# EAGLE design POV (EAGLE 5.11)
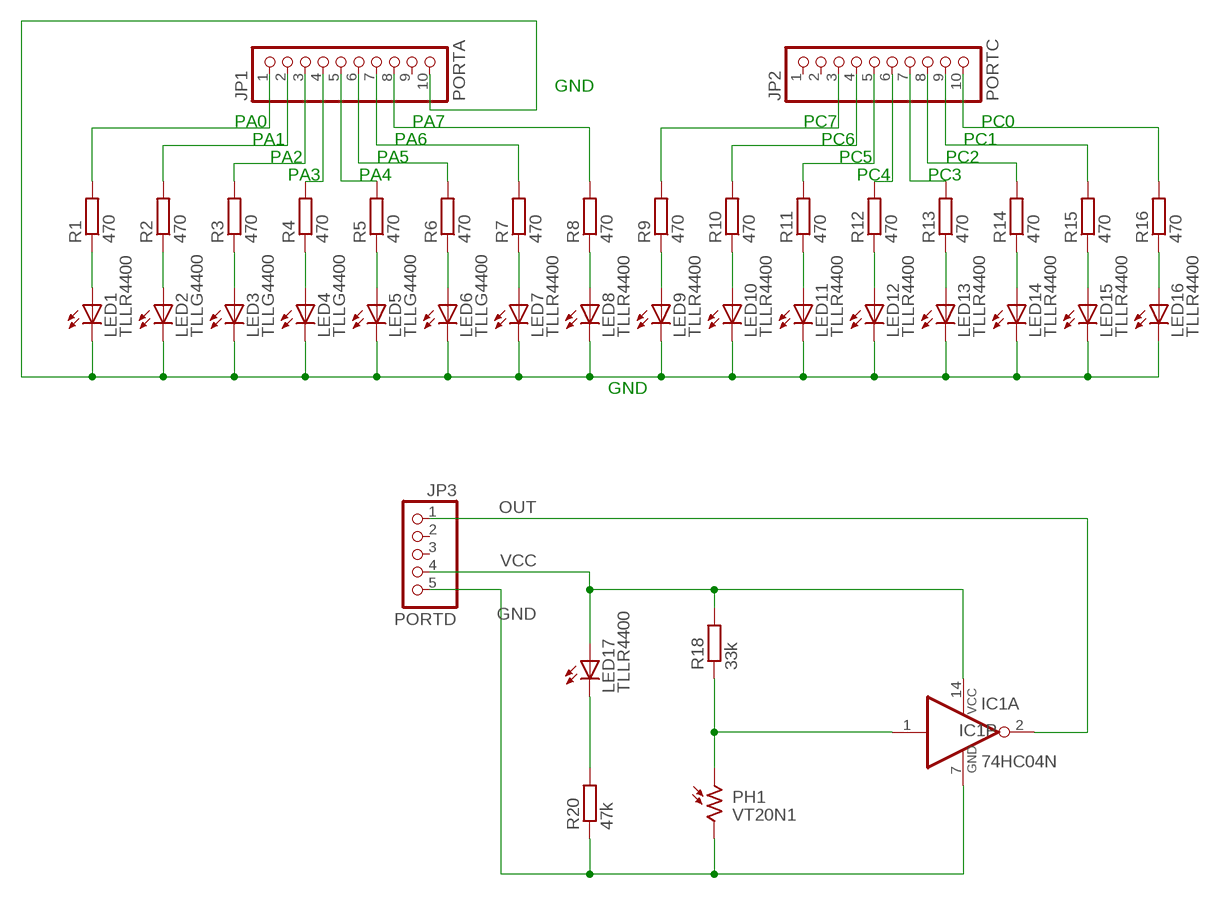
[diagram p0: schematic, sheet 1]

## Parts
IC1  74HC04N  [DIL14]
JP1  PORTA  PINHD-1X10  [1X10]
JP2  PORTC  PINHD-1X10  [1X10]
JP3  PORTD  PINHD-1X5  [1X05]
LED1  TLLR4400  LED5MM  [LED5MM]
LED2  TLLG4400  LED5MM  [LED5MM]
LED3  TLLG4400  LED5MM  [LED5MM]
LED4  TLLG4400  LED5MM  [LED5MM]
LED5  TLLG4400  LED5MM  [LED5MM]
LED6  TLLG4400  LED5MM  [LED5MM]
LED7  TLLR4400  LED5MM  [LED5MM]
LED8  TLLR4400  LED5MM  [LED5MM]
LED9  TLLR4400  LED5MM  [LED5MM]
LED10  TLLR4400  LED5MM  [LED5MM]
LED11  TLLR4400  LED5MM  [LED5MM]
LED12  TLLR4400  LED5MM  [LED5MM]
LED13  TLLR4400  LED5MM  [LED5MM]
LED14  TLLR4400  LED5MM  [LED5MM]
LED15  TLLR4400  LED5MM  [LED5MM]
LED16  TLLR4400  LED5MM  [LED5MM]
LED17  TLLR4400  LED5MM  [LED5MM]
PH1  VT20N1  [TO46-VT200]
R1  470  R-EU_0207/10  [0207/10]
R2  470  R-EU_0207/10  [0207/10]
R3  470  R-EU_0207/10  [0207/10]
R4  470  R-EU_0207/10  [0207/10]
R5  470  R-EU_0207/10  [0207/10]
R6  470  R-EU_0207/10  [0207/10]
R7  470  R-EU_0207/10  [0207/10]
R8  470  R-EU_0207/10  [0207/10]
R9  470  R-EU_0207/10  [0207/10]
R10  470  R-EU_0207/10  [0207/10]
R11  470  R-EU_0207/10  [0207/10]
R12  470  R-EU_0207/10  [0207/10]
R13  470  R-EU_0207/10  [0207/10]
R14  470  R-EU_0207/10  [0207/10]
R15  470  R-EU_0207/10  [0207/10]
R16  470  R-EU_0207/10  [0207/10]
R18  33k  R-EU_0207/10  [0207/10]
R20  47k  R-EU_0207/10  [0207/10]

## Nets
GND: IC1.7(P:GND) JP3.5 PH1.2 R20.1
N$1: LED1.A R1.1
N$2: LED2.A R2.1
N$3: LED3.A R3.1
N$4: LED4.A R4.1
N$5: LED5.A R5.1
N$6: LED6.A R6.1
N$7: LED7.A R7.1
N$8: LED8.A R8.1
N$9: LED9.A R9.1
N$10: LED10.A R10.1
N$11: LED11.A R11.1
N$12: LED12.A R12.1
N$13: JP1.7 R7.2
N$14: JP1.8 R8.2
N$15: JP1.3 R3.2
N$16: JP1.4 R4.2
N$17: JP1.5 R5.2
N$18: JP1.6 R6.2
N$19: JP1.2 R2.2
N$20: JP1.1 R1.2
N$21: LED17.K(C) R20.2
N$22: JP2.5 R11.2
N$23: JP2.4 R10.2
N$24: JP2.3 R9.2
N$25: LED13.A R13.1
N$26: LED14.A R14.1
N$27: LED15.A R15.1
N$28: LED16.A R16.1
N$29: JP2.7 R13.2
N$30: JP2.8 R14.2
N$31: JP2.9 R15.2
N$32: JP2.10 R16.2
N$33: JP1.10 LED1.K(C) LED2.K(C) LED3.K(C) LED4.K(C) LED5.K(C) LED6.K(C) LED7.K(C) LED8.K(C) LED9.K(C) LED10.K(C) LED11.K(C) LED12.K(C) LED13.K(C) LED14.K(C) LED15.K(C) LED16.K(C)
N$34: JP2.6 R12.2
N$37: IC1.1(A:I) PH1.1 R18.1
OUT: IC1.2(A:O) JP3.1
VCC: IC1.14(P:VCC) JP3.4 LED17.A R18.2
Unconnected: IC1.3(B:I) IC1.4(B:O) IC1.5(C:I) IC1.6(C:O) IC1.8(D:O) IC1.9(D:I) IC1.10(E:O) IC1.11(E:I) IC1.12(F:O) IC1.13(F:I) JP1.9 JP2.1 JP2.2 JP3.2 JP3.3

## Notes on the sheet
- GND
- PA0 | PA7 | PC7 | PC0
- PA1 | PA6 | PC6 | PC1
- PA2 | PA5 | PC5 | PC2
- PA3 | PA4 | PC4 | PC3
- GND

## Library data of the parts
IC1 = 74xx-eu:74*04: Hex INVERTER
JP1 JP2 = pinhead:PINHD-1X10: PIN HEADER
JP3 = pinhead:PINHD-1X5: PIN HEADER
LED1-LED17 = led:LED: LED
PH1 = photo-elements:VT2*: Photoconductive Cell VT200 Series
R1-R16 R18 R20 = resistor:R-EU_: RESISTOR, European symbol

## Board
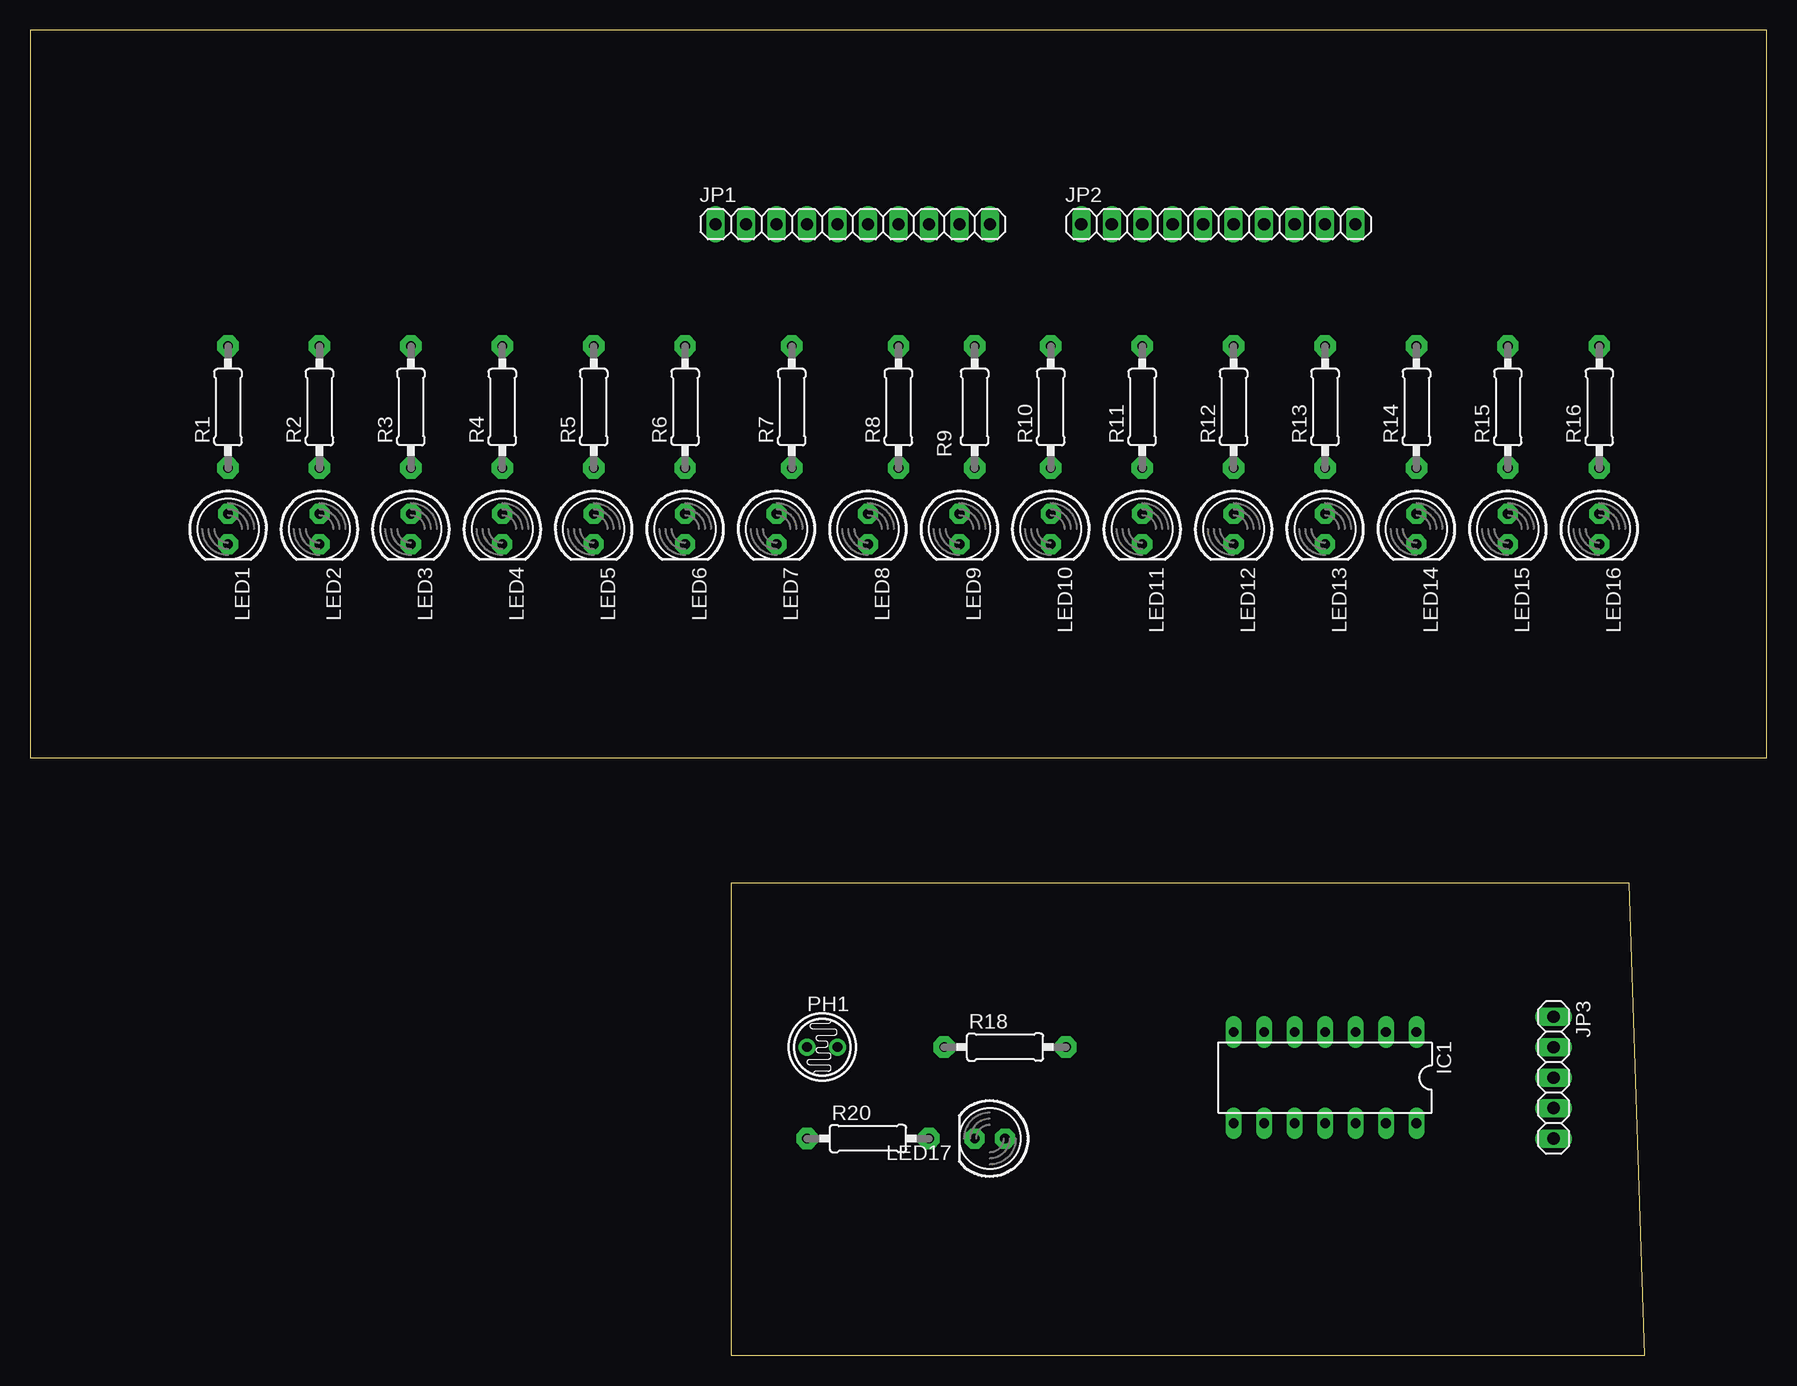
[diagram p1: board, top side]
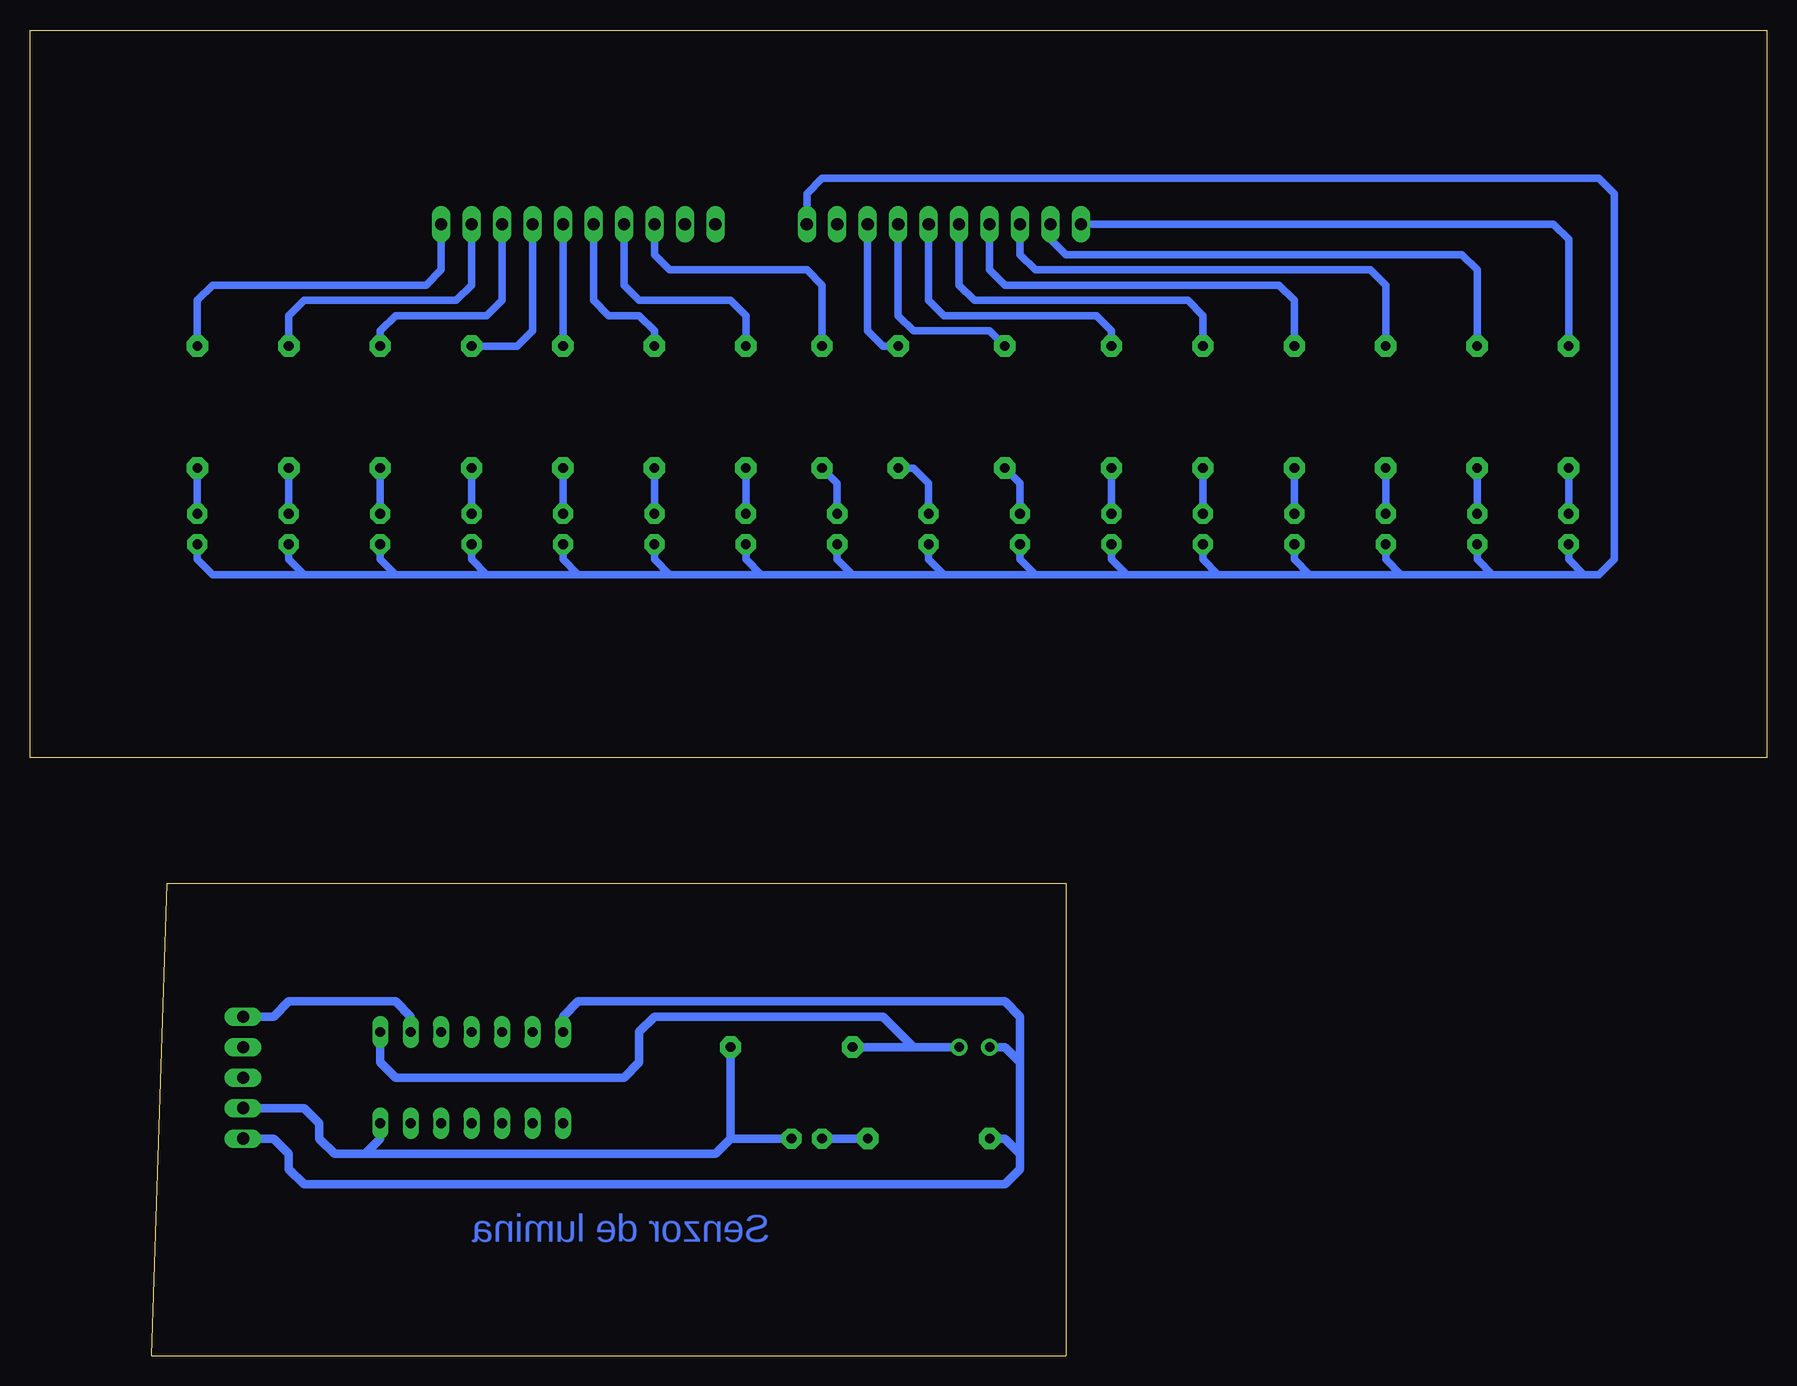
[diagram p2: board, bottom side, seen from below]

Size 144.76 x 110.49 mm. Coordinates in mm from the lower left corner, seen from the top.
Outline: 0,49.86 144.76,49.86 144.76,110.49 0,110.49 0,49.86
Outline: 133.33,39.37 58.42,39.37 58.42,0 134.6,0 133.33,39.37
Copper layers (1*16): Top 0.035mm / dielectric 1.5mm / Bottom 0.035mm
Design rules "default *": minimum track width 10mil, minimum drill 8mil, track to track 8mil, track to pad 8mil, pad to pad 8mil, via to via 8mil, smd to smd 8mil, copper to edge 10mil, drill to drill 8mil, minimum pad ring 10mil, minimum via ring 8mil, stop-mask expansion 4mil, vias tented up to drill 0mil, thermal gap 10mil

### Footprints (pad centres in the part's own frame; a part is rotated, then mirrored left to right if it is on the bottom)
DIL14 = drill 0.813 long: 1 -7.62,-3.81; 2 -5.08,-3.81; 3 -2.54,-3.81; 4 0,-3.81; 5 2.54,-3.81; 6 5.08,-3.81; 7 7.62,-3.81; 8 7.62,3.81; 9 5.08,3.81; 10 2.54,3.81; 11 0,3.81; 12 -2.54,3.81; 13 -5.08,3.81; 14 -7.62,3.81
1X10 = drill 1.016 long: 1 -11.43,0; 2 -8.89,0; 3 -6.35,0; 4 -3.81,0; 5 -1.27,0; 6 1.27,0; 7 3.81,0; 8 6.35,0; 9 8.89,0; 10 11.43,0
1X05 = drill 1.016 long: 1 -5.08,0; 2 -2.54,0; 3 0,0; 4 2.54,0; 5 5.08,0
LED5MM = drill 0.813 pad 1.676 octagon: A -1.27,0; K 1.27,0
TO46-VT200 = drill 0.8 pad 1.4 round: 1 -1.27,0; 2 1.27,0
0207/10 = drill 0.813 pad 1.778 octagon: 1 -5.08,0; 2 5.08,0

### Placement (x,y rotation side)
IC1  107.95,23.19 180 top
JP1  68.58,94.31 0 top
JP2  99.06,94.31 0 top
JP3  127,23.19 270 top
LED1  16.51,68.91 270 top
LED2  24.13,68.91 270 top
LED3  31.75,68.91 270 top
LED4  39.37,68.91 270 top
LED5  46.99,68.91 270 top
LED6  54.61,68.91 270 top
LED7  62.23,68.91 270 top
LED8  69.85,68.91 270 top
LED9  77.47,68.91 270 top
LED10  85.09,68.91 270 top
LED11  92.71,68.91 270 top
LED12  100.33,68.91 270 top
LED13  107.95,68.91 270 top
LED14  115.57,68.91 270 top
LED15  123.19,68.91 270 top
LED16  130.81,68.91 270 top
LED17  80.01,18.11 180 top
PH1  66.04,25.73 180 top
R1  16.51,79.07 90 top
R2  24.13,79.07 90 top
R3  31.75,79.07 90 top
R4  39.37,79.07 90 top
R5  46.99,79.07 90 top
R6  54.61,79.07 90 top
R7  63.5,79.07 90 top
R8  72.39,79.07 90 top
R9  78.74,79.07 90 top
R10  85.09,79.07 90 top
R11  92.71,79.07 90 top
R12  100.33,79.07 90 top
R13  107.95,79.07 90 top
R14  115.57,79.07 90 top
R15  123.19,79.07 90 top
R16  130.81,79.07 90 top
R18  81.28,25.73 0 top
R20  69.85,18.11 0 top

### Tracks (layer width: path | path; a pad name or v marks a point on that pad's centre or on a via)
GND
  Bottom 0.711: IC1.7 100.33,28.27 99.06,29.54 63.5,29.54 62.23,28.27 62.23,24.46 | 62.23,16.84 62.23,15.57 63.5,14.3 121.92,14.3 123.19,15.57 123.19,16.84 124.46,18.11 JP3.5 | 62.23,16.84 62.23,24.46 | PH1.2 63.5,25.73 62.23,24.46 | R20.1 63.5,18.11 62.23,16.84
N$1
  Bottom 0.61: LED1.A R1.1
N$2
  Bottom 0.61: LED2.A R2.1
N$3
  Bottom 0.61: LED3.A R3.1
N$4
  Bottom 0.61: LED4.A R4.1
N$5
  Bottom 0.61: LED5.A R5.1
N$6
  Bottom 0.61: LED6.A R6.1
N$7
  Bottom 0.61: LED7.A 62.23,72.72 R7.1
N$8
  Bottom 0.61: LED8.A 69.85,72.72 71.12,73.99 R8.1
N$9
  Bottom 0.61: LED9.A 77.47,72.72 R9.1
N$10
  Bottom 0.61: LED10.A R10.1
N$11
  Bottom 0.61: LED11.A R11.1
N$12
  Bottom 0.61: LED12.A R12.1
N$13
  Bottom 0.61: JP1.7 72.39,86.69 71.12,85.42 64.77,85.42 R7.2
N$14
  Bottom 0.61: R8.2 73.66,84.15 74.93,85.42 JP1.8
N$15
  Bottom 0.61: R3.2 31.75,89.23 33.02,90.5 60.96,90.5 62.23,91.77 JP1.3
N$16
  Bottom 0.61: R4.2 39.37,87.96 40.64,89.23 63.5,89.23 64.77,90.5 JP1.4
N$17
  Bottom 0.61: R5.2 46.99,86.69 48.26,87.96 66.04,87.96 67.31,89.23 JP1.5
N$18
  Bottom 0.61: R6.2 54.61,85.42 55.88,86.69 68.58,86.69 69.85,87.96 JP1.6
N$19
  Bottom 0.61: R2.2 24.13,90.5 25.4,91.77 58.42,91.77 59.69,93.04 JP1.2
N$20
  Bottom 0.61: R1.2 16.51,93.04 17.78,94.31 JP1.1
N$21
  Bottom 0.711: R20.2 LED17.K
N$22
  Bottom 0.61: R11.2 92.71,85.42 93.98,86.69 96.52,86.69 97.79,87.96 JP2.5
N$23
  Bottom 0.61: R10.2 85.09,86.69 86.36,87.96 93.98,87.96 95.25,89.23 JP2.4
N$24
  Bottom 0.61: JP2.3 92.71,91.77 91.44,90.5 80.01,90.5 78.74,89.23 R9.2
N$25
  Bottom 0.61: LED13.A R13.1
N$26
  Bottom 0.61: LED14.A R14.1
N$27
  Bottom 0.61: LED15.A R15.1
N$28
  Bottom 0.61: LED16.A R16.1
N$29
  Bottom 0.61: R13.2 104.14,84.15 102.87,85.42 JP2.7
N$30
  Bottom 0.61: JP2.8 105.41,87.96 106.68,86.69 114.3,86.69 115.57,85.42 R14.2
N$31
  Bottom 0.61: R15.2 123.19,86.69 121.92,87.96 109.22,87.96 107.95,89.23 JP2.9
N$32
  Bottom 0.61: R16.2 130.81,87.96 129.54,89.23 111.76,89.23 110.49,90.5 JP2.10
N$33
  Bottom 0.61: JP1.10 80.01,96.85 78.74,98.12 13.97,98.12 12.7,96.85 12.7,66.37 13.97,65.1 15.24,65.1 | 15.24,65.1 16.51,66.37 LED1.K | LED2.K 24.13,66.37 22.86,65.1 | 15.24,65.1 22.86,65.1 | LED16.K 130.81,66.37 129.54,65.1 121.92,65.1 | 22.86,65.1 30.48,65.1 | 30.48,65.1 38.1,65.1 | 38.1,65.1 45.72,65.1 | 45.72,65.1 53.34,65.1 | 53.34,65.1 60.96,65.1 | 60.96,65.1 68.58,65.1 | 68.58,65.1 76.2,65.1 | 76.2,65.1 83.82,65.1 | 83.82,65.1 91.44,65.1 | 91.44,65.1 99.06,65.1 | 99.06,65.1 106.68,65.1 | 106.68,65.1 114.3,65.1 | 114.3,65.1 121.92,65.1 | LED15.K 123.19,66.37 121.92,65.1 | LED14.K 115.57,66.37 114.3,65.1 | LED13.K 107.95,66.37 106.68,65.1 | LED12.K 100.33,66.37 99.06,65.1 | LED11.K 92.71,66.37 91.44,65.1 | LED10.K 85.09,66.37 83.82,65.1 | LED9.K 77.47,66.37 76.2,65.1 | LED8.K 69.85,66.37 68.58,65.1 | LED7.K 62.23,66.37 60.96,65.1 | LED6.K 54.61,66.37 53.34,65.1 | LED5.K 46.99,66.37 45.72,65.1 | LED4.K 39.37,66.37 38.1,65.1 | LED3.K 31.75,66.37 30.48,65.1
N$34
  Bottom 0.61: R12.2 JP2.6
N$37
  Bottom 0.711: 71.12,25.73 73.66,28.27 92.71,28.27 93.98,27 93.98,24.46 95.25,23.19 114.3,23.19 115.57,24.46 IC1.1 | PH1.1 71.12,25.73 | 71.12,25.73 R18.1
OUT
  Bottom 0.711: IC1.2 113.03,28.27 114.3,29.54 123.19,29.54 124.46,28.27 JP3.1
VCC
  Bottom 0.711: IC1.14 115.57,18.11 116.84,16.84 | 116.84,16.84 87.63,16.84 86.36,18.11 | 86.36,18.11 R18.2 | LED17.A 86.36,18.11 | 116.84,16.84 119.38,16.84 120.65,18.11 120.65,19.38 121.92,20.65 JP3.4

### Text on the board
Bottom: Senzor de lumina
